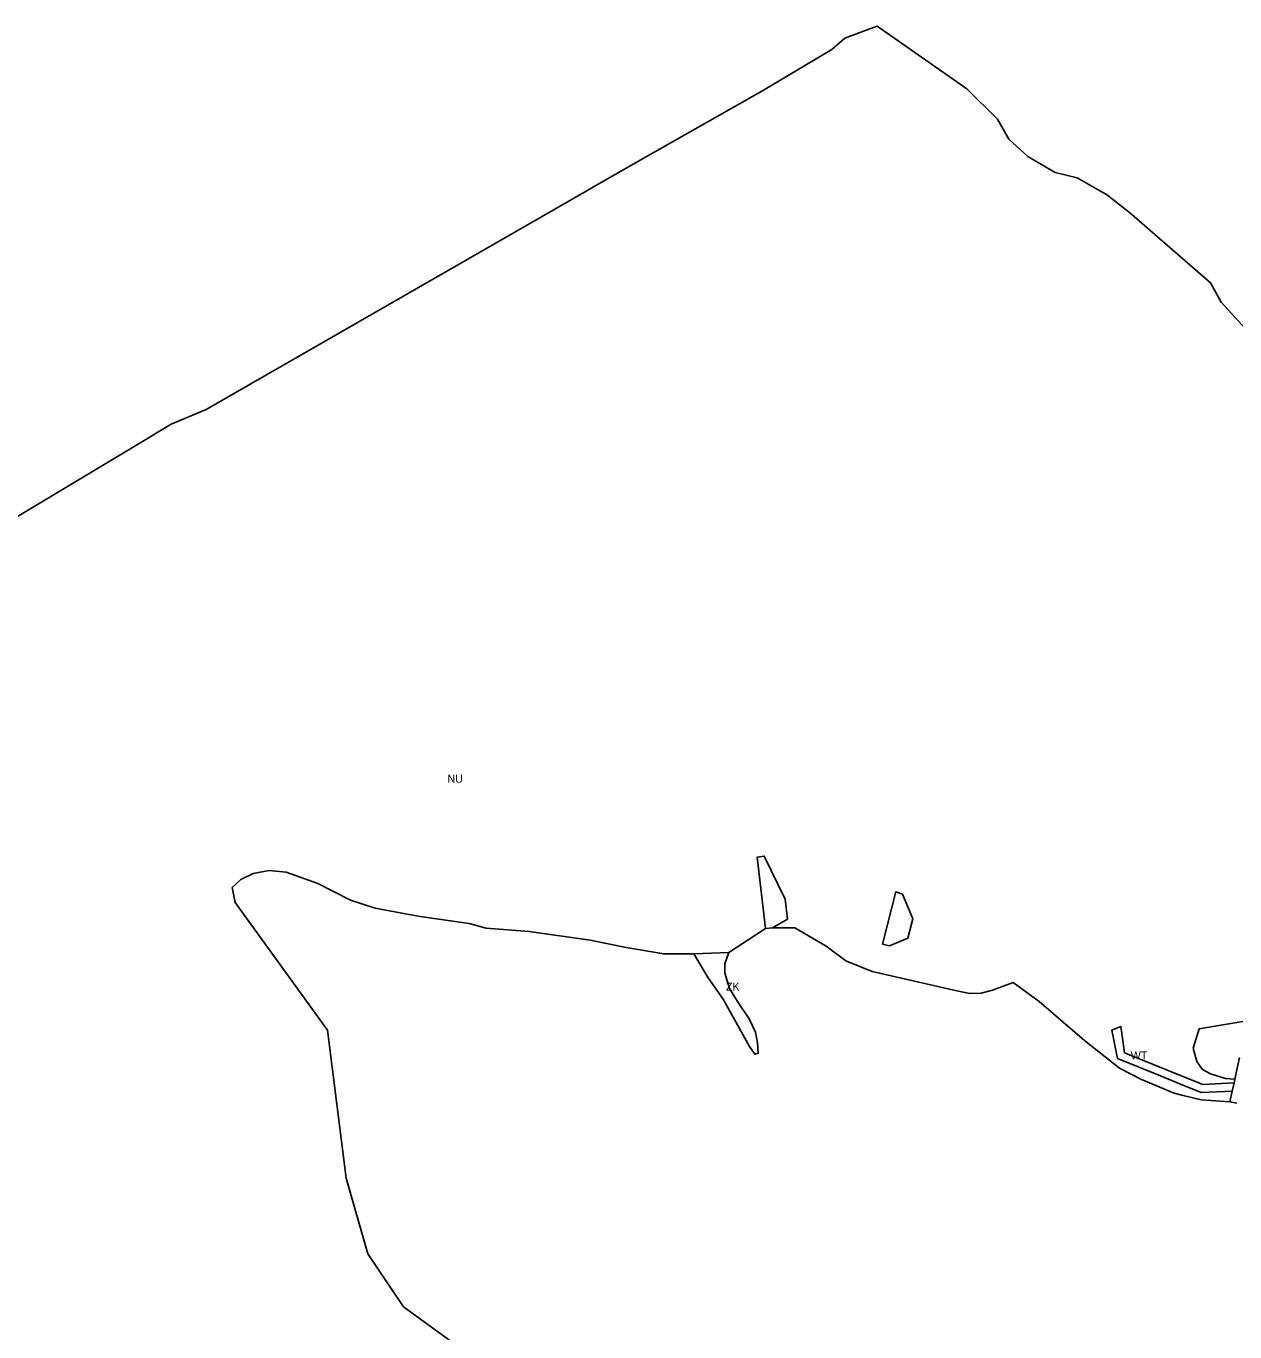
# Model space of a CAD drawing. Extents: x -535894 to -532834, y -1165802 to -1163647.
# Drawn here: x -535102 to -534347, y -1164462 to -1163647 of the extents above; entities that cross this region are included whole.
import ezdxf

# ---------------------------------------------------------------- set-up
doc = ezdxf.new("R2010")
doc.units = 0
for name, color, linetype in [('Vrstva 16', 7, 'Continuous'), ('Vrstva 19', 7, 'Continuous'), ('Vrstva 20', 7, 'Continuous'), ('Vrstva 22', 7, 'Continuous'), ('Vrstva 4', 7, 'Continuous')]:
    doc.layers.add(name, color=color, linetype=linetype)

msp = doc.modelspace()

# ---------------------------------------------------------------- linework, layer by layer
at = {"layer": 'Vrstva 16'}
msp.add_lwpolyline([(-534663.54, -1164225.41), (-534666.11, -1164232.61), (-534666.11, -1164238.39), (-534663.22, -1164247.92), (-534658.17, -1164256.15), (-534650.95, -1164266.98), (-534646.91, -1164275.21), (-534645.61, -1164281.85), (-534645.32, -1164288.49), (-534647.377, -1164289.043), (-534650.553, -1164284.21), (-534667.134, -1164254.724), (-534676.36, -1164241.4), (-534685.41, -1164226.35)], close=True, dxfattribs=at)
at = {"layer": 'Vrstva 19'}
for points in [[(-535193.05, -1164004.23), (-535025.69, -1163903.86), (-535021.19, -1163901.16), (-535011.93, -1163895.61), (-534990.07, -1163886.45), (-534752.66, -1163750.06), (-534749.05, -1163747.99), (-534718.97, -1163730.71), (-534642.84, -1163687.62), (-534599.15, -1163661.49), (-534591.03, -1163654.51), (-534583.72, -1163651.75), (-534579.5, -1163650.15), (-534570.98, -1163646.93), (-534514.86, -1163686.14), (-534495.67, -1163705.05), (-534488.62, -1163717.48), (-534476.78, -1163728.4), (-534459.7, -1163738.33), (-534445.87, -1163741.61), (-534431.31, -1163750.05), (-534427.72, -1163752.13), (-534413.24, -1163763.36), (-534362.72, -1163807.37), (-534355.93, -1163819.24), (-534338.84, -1163838.27)], [(-534335.13, -1164267.45), (-534369.81, -1164273.2), (-534373.54, -1164285.18), (-534371.26, -1164293.52), (-534367.73, -1164298.58), (-534362.68, -1164301.36), (-534353.37, -1164304.203), (-534347.47, -1164304.55), (-534347.994, -1164306.993), (-534367.58, -1164307.92), (-534390.256, -1164298.692), (-534416.31, -1164288.09), (-534418.8, -1164271.7), (-534420.762, -1164272.492), (-534422.39, -1164273.15), (-534424.3, -1164273.92), (-534420.68, -1164291.71), (-534393.822, -1164302.637), (-534381.33, -1164307.72), (-534368.45, -1164312.96), (-534349.078, -1164312.05), (-534350.52, -1164318.78), (-534368.42, -1164317.5), (-534380.51, -1164314.71), (-534385.3, -1164313.34), (-534405.79, -1164304.82), (-534419.47, -1164297.82), (-534441.39, -1164280.53), (-534469.68, -1164256.06), (-534485.85, -1164244.28), (-534498.96, -1164248.96), (-534506.03, -1164250.83), (-534513.1, -1164251.12), (-534517.155, -1164250.247), (-534521.14, -1164249.39), (-534573.95, -1164237.35), (-534590.55, -1164230.7), (-534602.67, -1164221.46), (-534622.278, -1164210.134), (-534636.34, -1164210.08), (-534626.89, -1164204.68), (-534628.3, -1164192.26), (-534641.46, -1164165.28), (-534645.78, -1164165.89), (-534640.71, -1164210.58), (-534663.54, -1164225.41), (-534685.41, -1164226.35), (-534704.16, -1164226.38), (-534727.737, -1164222.305), (-534750.145, -1164217.86), (-534788.364, -1164212.453), (-534815.03, -1164210.32), (-534825.67, -1164207.45), (-534856.42, -1164203.12), (-534865.518, -1164201.4), (-534884.45, -1164197.82), (-534899.86, -1164192.76), (-534920.32, -1164182.4), (-534940.02, -1164175.33), (-534950.63, -1164174.32), (-534960.73, -1164176.08), (-534968.31, -1164179.87), (-534973.86, -1164184.93), (-534971.925, -1164194.304), (-534914.181, -1164273.951), (-534902.541, -1164366.459), (-534888.99, -1164413.7), (-534866.733, -1164446.894), (-534817.509, -1164482.62)]]:
    msp.add_lwpolyline(points, dxfattribs=at)
msp.add_lwpolyline([(-534567.49, -1164220.26), (-534563.23, -1164221.34), (-534551.69, -1164216.52), (-534548.63, -1164204.4), (-534555.08, -1164189.08), (-534559.25, -1164187.61)], close=True, dxfattribs=at)
at = {"layer": 'Vrstva 20'}
msp.add_lwpolyline([(-534344.59, -1164291.11), (-534347.47, -1164304.55), (-534353.37, -1164304.203), (-534362.68, -1164301.36), (-534367.73, -1164298.58), (-534371.26, -1164293.52), (-534373.54, -1164285.18), (-534369.81, -1164273.2), (-534335.13, -1164267.45)], dxfattribs=at)
at = {"layer": 'Vrstva 22'}
msp.add_lwpolyline([(-534817.509, -1164482.62), (-534866.733, -1164446.894), (-534888.99, -1164413.7), (-534902.541, -1164366.459), (-534914.181, -1164273.951), (-534971.925, -1164194.304), (-534973.86, -1164184.93), (-534968.31, -1164179.87), (-534960.73, -1164176.08), (-534950.63, -1164174.32), (-534940.02, -1164175.33), (-534920.32, -1164182.4), (-534899.86, -1164192.76), (-534884.45, -1164197.82), (-534865.518, -1164201.4), (-534856.42, -1164203.12), (-534825.67, -1164207.45), (-534815.03, -1164210.32), (-534788.364, -1164212.453), (-534750.145, -1164217.86), (-534727.737, -1164222.305), (-534704.16, -1164226.38), (-534685.41, -1164226.35), (-534676.36, -1164241.4), (-534667.134, -1164254.724), (-534650.553, -1164284.21), (-534647.377, -1164289.043), (-534645.32, -1164288.49), (-534645.61, -1164281.85), (-534646.91, -1164275.21), (-534650.95, -1164266.98), (-534658.17, -1164256.15), (-534663.22, -1164247.92), (-534666.11, -1164238.39), (-534666.11, -1164232.61), (-534663.54, -1164225.41), (-534640.71, -1164210.58), (-534636.34, -1164210.08), (-534622.278, -1164210.134), (-534602.67, -1164221.46), (-534590.55, -1164230.7), (-534573.95, -1164237.35), (-534521.14, -1164249.39), (-534517.155, -1164250.247), (-534513.1, -1164251.12), (-534506.03, -1164250.83), (-534498.96, -1164248.96), (-534485.85, -1164244.28), (-534469.68, -1164256.06), (-534441.39, -1164280.53), (-534419.47, -1164297.82), (-534405.79, -1164304.82), (-534385.3, -1164313.34), (-534380.51, -1164314.71), (-534368.42, -1164317.5), (-534350.52, -1164318.78), (-534346.22, -1164319.71)], dxfattribs=at)
at = {"layer": 'Vrstva 4'}
msp.add_lwpolyline([(-534420.762, -1164272.492), (-534418.8, -1164271.7), (-534416.31, -1164288.09), (-534390.256, -1164298.692), (-534367.58, -1164307.92), (-534347.994, -1164306.993), (-534349.078, -1164312.05), (-534368.45, -1164312.96), (-534381.33, -1164307.72), (-534393.822, -1164302.637), (-534420.68, -1164291.71), (-534424.3, -1164273.92), (-534422.39, -1164273.15)], close=True, dxfattribs=at)

# ---------------------------------------------------------------- texts
at = {"layer": 'Vrstva 16'}
msp.add_text('ZK', height=5, rotation=360, dxfattribs=at).set_placement((-534665.365, -1164249.3583))
at = {"layer": 'Vrstva 19'}
msp.add_text('NU', height=5, rotation=0.0000001, dxfattribs=at).set_placement((-534839.273, -1164119.48))
at = {"layer": 'Vrstva 4'}
msp.add_text('WT', height=5, rotation=360, dxfattribs=at).set_placement((-534412.5232, -1164292.33))

doc.saveas('drawing.dxf')
